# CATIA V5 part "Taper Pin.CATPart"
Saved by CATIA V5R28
Part number: Taper Pin
Bounding box of the stored display mesh (mm): x -1.919 to 1.919, y -15 to 15, z -1.919 to 1.919
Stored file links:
  C:\Users\Parisa\Desktop\tarah sanat\Universal Coupling\Taper Pin.CATPart
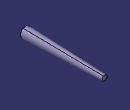
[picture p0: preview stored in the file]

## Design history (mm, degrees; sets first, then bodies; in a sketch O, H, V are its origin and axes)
Body1 "Taper Pin" (main body)
  Sketch1 on yz-plane, origin (0, 0, 0), H (0, 1, 0), V (0, 0, 1)
    line L1 (0, 0) -> (15, 0)
    point P1 (15, 0)
    point P2 (-15, 0)
    point P3 (0, 0)
    line L2 (0, 0) -> (-15, 0)
    line L3 (-15, 0) -> (-15, 2)
    line L4 (-15, 2) -> (15, 0.9996)
    line L5 (15, 0.9996) -> (15, 0)
    point P6 (15, 0)
    length L1 = 15
    length L3 = 2
    angle L3 L4 = 88.09
    distance P1 P6 = 0
    horizontal: L1 H
    symmetry: P1 P2 V, O P3 V, L1 L2 V
    vertical: L3 V, L5 V
    coincidence: O P3
  Shaft1: profile Sketch1, axis Sketch1.L2, angle 360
